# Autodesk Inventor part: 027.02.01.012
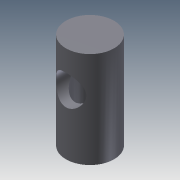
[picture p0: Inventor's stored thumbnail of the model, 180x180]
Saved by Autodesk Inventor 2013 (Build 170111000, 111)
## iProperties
Shininess: 64.0
Length Units: 11269
Angle Units: 11279
Time Units: 11290
Mass Units: 11283
Length Display Precision: 3
Angle Display Precision: 2
Created: 2003-04
Part Number: 027.02.01.012
Material: Steel, Mild
Document SubType Name: Modeling
Designer: NAndrey
Density: 1 g/cm^3
Density: 0.0
Volumn: 0.0
Area: 0.0
PropertySet Name: Model Information
Control State: 0
Master: False
Checked Out: True
Checked Out Date: 2008-10-15
Last Check In Date: 2008-10-15
Author: NAndrey
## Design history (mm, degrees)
sketch "Sketch1"
  geometry: C1 r 20 at (0, 0)
  constraints: 1 centre point
  dimensions: "d0" = 40 diameter of C1
extrude "Extrusion1" new body sketch "Sketch1" distance "d1" = 80; taper "d2" = 0 deg
sketch "Sketch2"
  geometry: C1 r 20 at (0, 0) reference
hole "Hole1" sketch "Sketch2" at (0, 0) diameter "d3" = 25; stored, may be unused: countersink angle "d7" = 82 deg, drill point angle "d9" = 120 deg; dims "d4" = 6, "d5" = 4, "d6" = 2, "d8" = 65
workaxis "Work Axis1"
workplane "Work Plane1"
workplane "Work Plane2"
sketch "Sketch3"
  geometry: L1 (0, 96)-(0, -16) reference; L2 (-20, 0)-(20, 0) reference; 1 further point
  constraints: 1 point on line
  dimensions: "d11" = 50 distance from line of point (0, 50) L2
hole "Hole2" sketch "Sketch3" at (0, 50) diameter "d12" = 25; stored, may be unused: countersink angle "d16" = 82 deg, drill point angle "d18" = 120 deg; dims "d13" = 6, "d14" = 4, "d15" = 2, "d17" = 20
body "Solid1"
other parameters: "d10" = 90 deg
